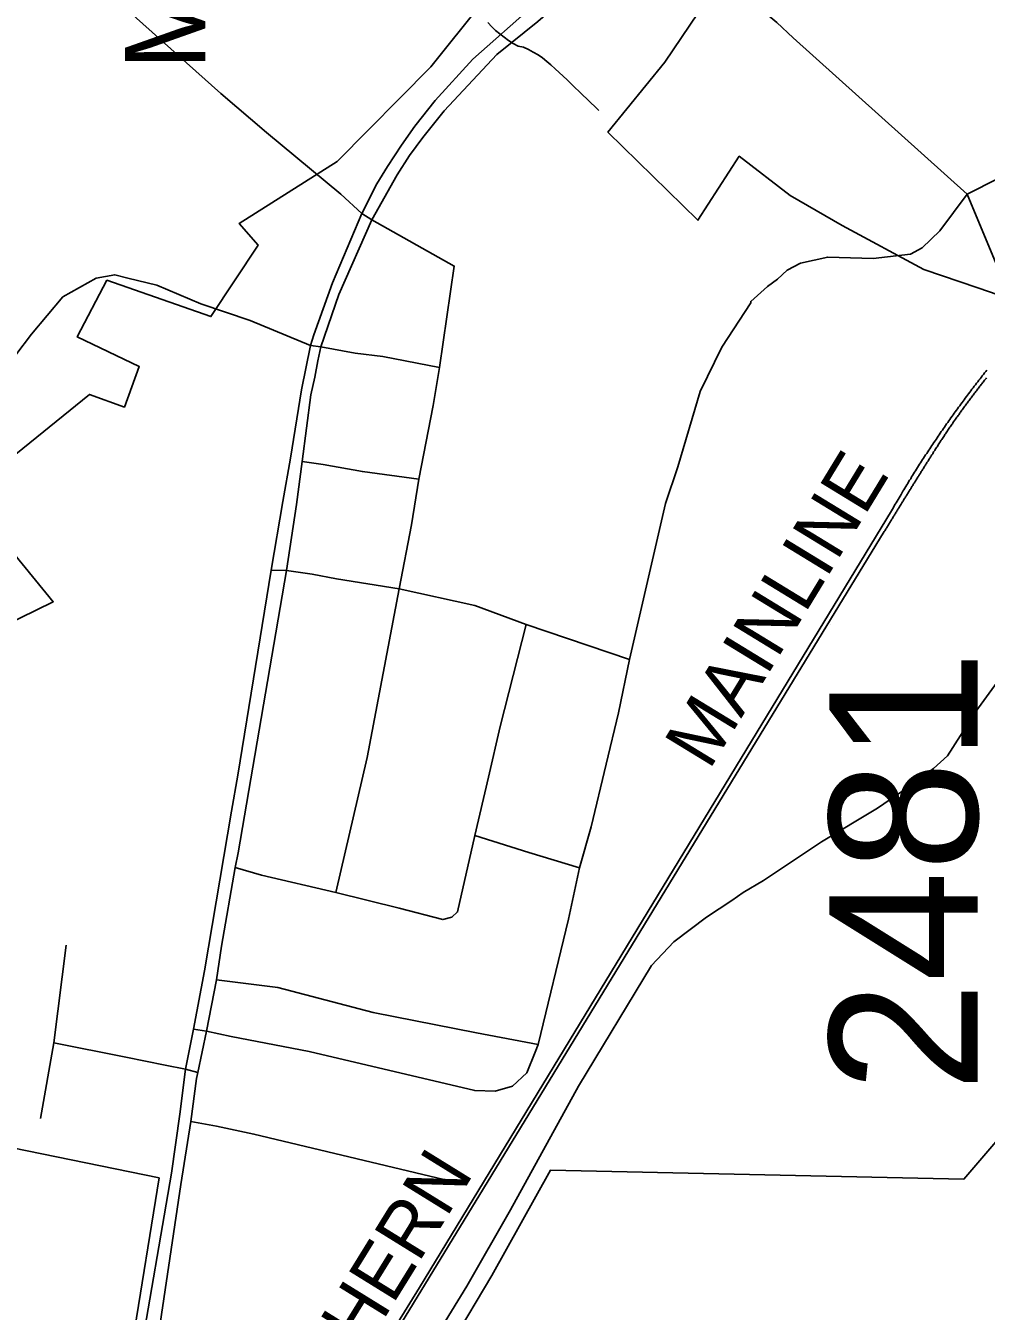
# Model space of a CAD drawing. Extents: x 1373043 to 1375788, y 550128 to 553055.
# Drawn here: x 1373223.9 to 1373314.3, y 550684.8 to 550805.7 of the extents above; entities that cross this region are included whole.
import ezdxf

# ---------------------------------------------------------------- set-up
doc = ezdxf.new("R2010")
doc.units = 0
for name, color, linetype in [('Old_Level_12', 7, 'Continuous'), ('Old_Level_14', 7, 'Continuous'), ('Old_Level_28', 7, 'Continuous'), ('Old_Level_32', 7, 'Continuous'), ('Old_Level_44', 7, 'Continuous'), ('Old_Level_48', 7, 'Continuous'), ('Old_Level_62', 7, 'Continuous'), ('Old_Level_9', 7, 'Continuous')]:
    doc.layers.add(name, color=color, linetype=linetype)

msp = doc.modelspace()

# ---------------------------------------------------------------- linework, layer by layer
at = {"layer": 'Old_Level_14'}
msp.add_line((1373299.6, 550749.45), (1373299.6, 550749.45), dxfattribs=at)
at = {"layer": 'Old_Level_28'}
for p, q in [((1373240.92, 550711.19), (1373241.85, 550716.02)), ((1373239.69, 550711.36), (1373238.96, 550707.59)), ((1373240.1, 550707.28), (1373240.92, 550711.19))]:
    msp.add_line(p, q, dxfattribs=at)
for points in [[(1373282.11, 550816.63), (1373278.35, 550813.16), (1373274.52, 550810.14), (1373271.67, 550807.62), (1373265.99, 550802.6), (1373262.43, 550798.7), (1373260.52, 550796.28), (1373259.28, 550794.52), (1373257.94, 550792.49), (1373256.94, 550790.87), (1373255.53, 550788.08)], [(1373256.48, 550787.5), (1373258.86, 550791.72), (1373260.04, 550793.52), (1373261.29, 550795.23), (1373263.28, 550797.75), (1373268.23, 550803.03), (1373272.1, 550806.14), (1373280.61, 550813.51), (1373280.75, 550813.7), (1373282.89, 550815.73)], [(1373255.53, 550788.08), (1373252.77, 550781.56), (1373251.01, 550776.67), (1373250.72, 550775.67)], [(1373251.69, 550775.53), (1373253.39, 550780.47), (1373256.48, 550787.5)], [(1373250.72, 550775.67), (1373249.86, 550771.49), (1373248.82, 550765.07), (1373248.1, 550761), (1373247, 550754.53)], [(1373249.94, 550764.76), (1373250.74, 550771.04), (1373251.12, 550772.7), (1373251.4, 550774.21), (1373251.69, 550775.53)], [(1373248.45, 550754.5), (1373249.39, 550760.72), (1373249.94, 550764.76)], [(1373247, 550754.53), (1373243.87, 550735.27), (1373243.28, 550731.88), (1373240.72, 550716.86), (1373239.69, 550711.36)], [(1373243.62, 550726.56), (1373243.89, 550727.94), (1373248.45, 550754.5)], [(1373241.85, 550716.02), (1373242.32, 550719.17), (1373243.62, 550726.56)], [(1373238.96, 550707.59), (1373238.42, 550703.37), (1373237.62, 550697.82), (1373234.6, 550680.13), (1373231.07, 550660.01)], [(1373239.46, 550702.69), (1373239.99, 550706.74), (1373240.1, 550707.28)], [(1373232.57, 550660.38), (1373236, 550679.89), (1373238.52, 550696.76), (1373239.46, 550702.69)]]:
    msp.add_lwpolyline(points, dxfattribs=at)
at = {"layer": 'Old_Level_32'}
for p, q in [((1373256.48, 550787.5), (1373255.53, 550788.08)), ((1373250.72, 550775.67), (1373251.69, 550775.53)), ((1373247, 550754.53), (1373248.45, 550754.5)), ((1373271, 550749.44), (1373280.74, 550746.13)), ((1373226.54, 550710.09), (1373227.71, 550719.27)), ((1373239.69, 550711.36), (1373240.92, 550711.19)), ((1373225.3, 550702.96), (1373226.54, 550710.09)), ((1373240.1, 550707.28), (1373238.96, 550707.59))]:
    msp.add_line(p, q, dxfattribs=at)
for points in [[(1373312.5, 550789.89), (1373315.41, 550791.38), (1373319.75, 550792.77), (1373327.67, 550794.97), (1373334.41, 550797.08), (1373339.3, 550798.67), (1373343.71, 550800.13), (1373350.28, 550802.37), (1373366.35, 550807.53), (1373371.49, 550809.06), (1373378.05, 550811.22), (1373381.15, 550812.18), (1373385.12, 550814.73), (1373386.58, 550815.99), (1373388.24, 550817.28), (1373391.43, 550821.07), (1373396.24, 550827.01), (1373405.03, 550836.86), (1373410.47, 550842.94), (1373418.29, 550852.16), (1373421.65, 550856)], [(1373255.53, 550788.08), (1373253.55, 550789.89), (1373246.56, 550795.7), (1373242.26, 550799.38), (1373233.47, 550807.25), (1373230.45, 550809.43), (1373229.43, 550810.16), (1373227.3, 550811.63), (1373226.31, 550812.39), (1373225.78, 550813.39), (1373226.26, 550815.62), (1373227.28, 550817.94)], [(1373282.89, 550815.73), (1373285.18, 550813.78), (1373288.65, 550811.17), (1373290.47, 550809.48), (1373292.26, 550807.99), (1373292.92, 550807.43), (1373294.58, 550806.04), (1373296.13, 550804.59), (1373312.5, 550789.89)], [(1373280.74, 550746.13), (1373284.13, 550760.81), (1373285.27, 550764.26), (1373287.37, 550771.33), (1373289.42, 550775.51), (1373292.15, 550779.68), (1373292.14, 550779.81), (1373293.7, 550781.22), (1373294.66, 550781.9), (1373295.58, 550782.74), (1373296.82, 550783.4), (1373299.38, 550783.98), (1373303.67, 550783.84), (1373307.18, 550784.24), (1373308.26, 550784.84), (1373309.92, 550786.46), (1373312.5, 550789.89)], [(1373312.5, 550789.89), (1373316.32, 550780.71), (1373317.99, 550777.43)], [(1373256.48, 550787.5), (1373264.23, 550783.14), (1373262.84, 550773.61)], [(1373221.47, 550772.83), (1373224.46, 550776.74), (1373227.4, 550780.24), (1373230.55, 550781.99), (1373232.29, 550782.32), (1373233.53, 550781.99), (1373236.26, 550781.33), (1373240.39, 550779.6), (1373245.02, 550778.03), (1373250.72, 550775.67)], [(1373251.69, 550775.53), (1373254.9, 550774.96), (1373257.52, 550774.63), (1373262.84, 550773.61)], [(1373262.84, 550773.61), (1373262.26, 550770.03), (1373260.91, 550763.08)], [(1373249.94, 550764.76), (1373251.9, 550764.48), (1373255.59, 550763.81), (1373260.91, 550763.08)], [(1373260.91, 550763.08), (1373260.2, 550758.79), (1373259.06, 550752.78)], [(1373248.45, 550754.5), (1373250.88, 550754.15), (1373253.17, 550753.71), (1373259.06, 550752.78)], [(1373259.06, 550752.78), (1373256.03, 550736.93), (1373253.1, 550724.23)], [(1373259.06, 550752.78), (1373266.16, 550751.22), (1373271, 550749.44)], [(1373266.17, 550729.59), (1373267.46, 550735.06), (1373268.56, 550739.83), (1373271, 550749.44)], [(1373276.01, 550726.54), (1373277.13, 550730.41), (1373278.52, 550736.28), (1373279.68, 550741.11), (1373280.74, 550746.13)], [(1373252.09, 550665.48), (1373265.43, 550687.21), (1373269.52, 550694.37), (1373275.93, 550706), (1373282.79, 550717.35), (1373284.9, 550719.58), (1373287.96, 550721.89), (1373290.35, 550723.46), (1373291.43, 550724.21), (1373293.33, 550725.36), (1373296.72, 550727.59), (1373298.79, 550729), (1373304.08, 550732.16), (1373307.13, 550734.24), (1373309.33, 550735.87), (1373310.67, 550737.07), (1373313.31, 550741.23), (1373315.32, 550743.99)], [(1373253.1, 550724.23), (1373259.04, 550722.76), (1373263.17, 550721.68), (1373264.02, 550721.91), (1373264.55, 550722.39), (1373266.17, 550729.59)], [(1373266.17, 550729.59), (1373271.24, 550727.98), (1373276.01, 550726.54)], [(1373243.62, 550726.56), (1373246.1, 550725.85), (1373253.1, 550724.23)], [(1373272.13, 550709.93), (1373274.99, 550721.71), (1373276.01, 550726.54)], [(1373241.85, 550716.02), (1373247.65, 550715.27), (1373256.61, 550712.92), (1373266.34, 550711.01), (1373272.13, 550709.93)], [(1373240.92, 550711.19), (1373243.23, 550710.69), (1373250.58, 550709.25), (1373266.16, 550705.59), (1373268.09, 550705.53), (1373269.71, 550706), (1373271.07, 550707.25), (1373271.84, 550709.19), (1373272.13, 550709.93)], [(1373238.96, 550707.59), (1373237.04, 550707.97), (1373233.32, 550708.73), (1373226.54, 550710.09)], [(1373239.46, 550702.69), (1373241.87, 550702.24), (1373245.39, 550701.5), (1373264.7, 550696.87)]]:
    msp.add_lwpolyline(points, dxfattribs=at)
at = {"layer": 'Old_Level_44'}
for points in [[(1373305.39, 550760.12), (1373305.48, 550760.28), (1373305.57, 550760.42), (1373305.65, 550760.58), (1373305.74, 550760.73), (1373305.83, 550760.88), (1373305.92, 550761.03), (1373306.01, 550761.19), (1373306.1, 550761.34), (1373306.19, 550761.49), (1373306.28, 550761.64), (1373306.37, 550761.79), (1373306.46, 550761.95), (1373306.55, 550762.09), (1373306.64, 550762.24), (1373306.73, 550762.4), (1373306.82, 550762.55), (1373306.91, 550762.69), (1373307, 550762.85), (1373307.09, 550763), (1373307.19, 550763.14), (1373307.28, 550763.3), (1373307.37, 550763.44), (1373307.46, 550763.59), (1373307.56, 550763.74), (1373307.65, 550763.89), (1373307.75, 550764.04), (1373307.84, 550764.19), (1373307.93, 550764.34), (1373308.03, 550764.49), (1373308.12, 550764.64), (1373308.22, 550764.78), (1373308.31, 550764.93), (1373308.41, 550765.08), (1373308.5, 550765.23), (1373308.6, 550765.37), (1373308.7, 550765.52), (1373308.79, 550765.67), (1373308.89, 550765.81), (1373308.99, 550765.96), (1373309.09, 550766.11), (1373309.18, 550766.26), (1373309.28, 550766.4), (1373309.38, 550766.55), (1373309.48, 550766.69), (1373309.58, 550766.84), (1373309.67, 550766.98), (1373309.78, 550767.13), (1373309.87, 550767.27), (1373309.97, 550767.42), (1373310.07, 550767.57), (1373310.17, 550767.71), (1373310.27, 550767.86), (1373310.37, 550768), (1373310.47, 550768.15), (1373310.57, 550768.29), (1373310.68, 550768.43), (1373310.78, 550768.58), (1373310.88, 550768.72), (1373310.98, 550768.86), (1373311.08, 550769.01), (1373311.19, 550769.15), (1373311.29, 550769.29), (1373311.39, 550769.44), (1373311.5, 550769.58), (1373311.6, 550769.72), (1373311.7, 550769.86), (1373311.81, 550770), (1373311.91, 550770.15), (1373312.02, 550770.29), (1373312.12, 550770.43), (1373312.22, 550770.57), (1373312.33, 550770.71), (1373312.43, 550770.86), (1373312.54, 550770.99), (1373312.64, 550771.13), (1373312.75, 550771.28), (1373312.86, 550771.41), (1373312.96, 550771.56), (1373313.07, 550771.69), (1373313.18, 550771.83), (1373313.28, 550771.97), (1373313.39, 550772.12), (1373313.5, 550772.25), (1373313.61, 550772.39), (1373313.72, 550772.53), (1373313.83, 550772.67), (1373313.93, 550772.81), (1373314.04, 550772.95), (1373314.15, 550773.08), (1373314.26, 550773.22), (1373314.37, 550773.36)], [(1373314.34, 550772.64), (1373314.28, 550772.56), (1373314.21, 550772.48), (1373314.14, 550772.4), (1373314.08, 550772.32), (1373314.02, 550772.23), (1373313.95, 550772.15), (1373313.89, 550772.07), (1373313.82, 550771.99), (1373313.76, 550771.91), (1373313.7, 550771.83), (1373313.63, 550771.74), (1373313.57, 550771.66), (1373313.51, 550771.58), (1373313.44, 550771.5), (1373313.38, 550771.41), (1373313.31, 550771.33), (1373313.25, 550771.25), (1373313.19, 550771.17), (1373313.13, 550771.08), (1373313.06, 550771), (1373313, 550770.92), (1373312.94, 550770.84), (1373312.88, 550770.75), (1373312.81, 550770.67), (1373312.75, 550770.59), (1373312.69, 550770.5), (1373312.63, 550770.42), (1373312.57, 550770.34), (1373312.5, 550770.25), (1373312.44, 550770.17), (1373312.38, 550770.09), (1373312.32, 550770), (1373312.26, 550769.92), (1373312.2, 550769.84), (1373312.13, 550769.75), (1373312.07, 550769.66), (1373312.01, 550769.58), (1373311.95, 550769.5), (1373311.89, 550769.41), (1373311.83, 550769.33), (1373311.77, 550769.24), (1373311.71, 550769.16), (1373311.65, 550769.08), (1373311.59, 550768.99), (1373311.53, 550768.91), (1373311.47, 550768.82), (1373311.41, 550768.74), (1373311.35, 550768.65), (1373311.29, 550768.57), (1373311.23, 550768.48), (1373311.17, 550768.39), (1373311.12, 550768.31), (1373311.06, 550768.22), (1373311, 550768.14), (1373310.94, 550768.06), (1373310.88, 550767.97), (1373310.82, 550767.88), (1373310.76, 550767.79), (1373310.7, 550767.71), (1373310.65, 550767.63), (1373310.59, 550767.54), (1373310.53, 550767.45), (1373310.47, 550767.36), (1373310.41, 550767.28), (1373310.36, 550767.19), (1373310.3, 550767.11), (1373310.24, 550767.02), (1373310.18, 550766.93), (1373310.13, 550766.84), (1373310.07, 550766.76), (1373310.01, 550766.67), (1373309.96, 550766.59), (1373309.9, 550766.5), (1373309.84, 550766.41), (1373309.79, 550766.33), (1373309.73, 550766.23), (1373309.67, 550766.15), (1373309.62, 550766.06), (1373309.56, 550765.98), (1373309.5, 550765.89), (1373309.45, 550765.8)], [(1373309.45, 550765.8), (1373309.4, 550765.72), (1373309.35, 550765.65), (1373309.3, 550765.57), (1373309.26, 550765.49), (1373309.21, 550765.42), (1373309.16, 550765.34), (1373309.11, 550765.26), (1373309.06, 550765.19), (1373309.01, 550765.11), (1373308.96, 550765.04), (1373308.92, 550764.96), (1373308.87, 550764.88), (1373308.82, 550764.8), (1373308.77, 550764.73), (1373308.72, 550764.65), (1373308.68, 550764.57), (1373308.63, 550764.5), (1373308.58, 550764.42), (1373308.53, 550764.34), (1373308.48, 550764.27), (1373308.43, 550764.19), (1373308.39, 550764.11), (1373308.34, 550764.04), (1373308.29, 550763.96), (1373308.24, 550763.88), (1373308.19, 550763.81), (1373308.14, 550763.73), (1373308.1, 550763.65), (1373308.05, 550763.57), (1373308, 550763.5), (1373307.95, 550763.42), (1373307.9, 550763.35), (1373307.86, 550763.27), (1373307.81, 550763.19), (1373307.76, 550763.11), (1373307.71, 550763.04), (1373307.66, 550762.96), (1373307.62, 550762.89), (1373307.57, 550762.81), (1373307.52, 550762.73), (1373307.47, 550762.65), (1373307.42, 550762.58), (1373307.38, 550762.5), (1373307.33, 550762.42), (1373307.28, 550762.35), (1373307.23, 550762.27), (1373307.19, 550762.19), (1373307.14, 550762.11), (1373307.09, 550762.04), (1373307.04, 550761.96), (1373306.99, 550761.88), (1373306.95, 550761.81), (1373306.9, 550761.73), (1373306.85, 550761.65), (1373306.8, 550761.57), (1373306.75, 550761.5), (1373306.71, 550761.42), (1373306.66, 550761.34), (1373306.61, 550761.27), (1373306.56, 550761.19), (1373306.52, 550761.11), (1373306.47, 550761.03), (1373306.42, 550760.96), (1373306.37, 550760.88), (1373306.32, 550760.8), (1373306.28, 550760.73), (1373306.23, 550760.65), (1373306.18, 550760.57), (1373306.13, 550760.5), (1373306.09, 550760.41), (1373306.04, 550760.34), (1373305.99, 550760.26), (1373305.95, 550760.19), (1373305.9, 550760.11), (1373305.85, 550760.03), (1373305.8, 550759.96), (1373305.75, 550759.88), (1373305.71, 550759.8), (1373305.66, 550759.72), (1373305.61, 550759.65), (1373305.57, 550759.57), (1373305.52, 550759.49), (1373305.47, 550759.41), (1373305.42, 550759.34), (1373305.38, 550759.26), (1373305.33, 550759.18), (1373305.28, 550759.1), (1373305.23, 550759.03), (1373305.19, 550758.95), (1373305.14, 550758.87), (1373305.09, 550758.79), (1373305.04, 550758.72), (1373305, 550758.64), (1373304.95, 550758.56), (1373304.9, 550758.49), (1373304.86, 550758.41), (1373304.81, 550758.33), (1373304.76, 550758.25), (1373304.71, 550758.18)], [(1373249.69, 550668.83), (1373260.97, 550687.07), (1373275.57, 550711.1), (1373305.39, 550760.12)], [(1373304.71, 550758.18), (1373266.98, 550696.37), (1373250.18, 550668.85)]]:
    msp.add_lwpolyline(points, dxfattribs=at)
at = {"layer": 'Old_Level_48'}
msp.add_line((1373229.83, 550656.55), (1373236.46, 550697.37), dxfattribs=at)
for points in [[(1373288.18, 550825.73), (1373285.86, 550822.58), (1373283.33, 550819.76), (1373279.11, 550815.95), (1373271.35, 550809.89), (1373273.73, 550815.44), (1373271.91, 550816.03), (1373270.15, 550813.04), (1373266.83, 550807.87), (1373262.04, 550801.86), (1373253.22, 550792.97)], [(1373336.32, 550729.83), (1373332.49, 550735.39), (1373330.4, 550744.08), (1373327.27, 550757.3), (1373324.14, 550766.34), (1373322.57, 550770.17), (1373320.48, 550774.86), (1373316.48, 550779.21), (1373315.43, 550780.42), (1373313.52, 550781.09), (1373308.44, 550782.81), (1373300.74, 550786.95), (1373295.84, 550789.77), (1373291.06, 550793.47), (1373287.17, 550787.45), (1373278.7, 550795.73), (1373284.06, 550802.32), (1373290.26, 550811.52)], [(1373253.22, 550792.97), (1373244, 550787.14), (1373245.78, 550785.1), (1373241.33, 550778.38), (1373231.55, 550781.8), (1373228.76, 550776.47), (1373234.6, 550773.68), (1373233.19, 550769.87), (1373229.92, 550771.07), (1373207.41, 550752.87), (1373207.43, 550751.22)], [(1373236.46, 550697.37), (1373183.99, 550708.12), (1373180.72, 550702.36), (1373165.88, 550718.26), (1373151.49, 550732.55), (1373139.62, 550743.77), (1373124.05, 550758.84), (1373109.22, 550773.14), (1373099.99, 550781.27), (1373088.48, 550768.94)], [(1373207.43, 550751.22), (1373222.9, 550755.97), (1373226.5, 550751.57), (1373207.88, 550742.46), (1373210.63, 550737.6), (1373198.07, 550740.79), (1373199.29, 550746.7)], [(1373372.48, 550663.67), (1373351.49, 550665.74), (1373346.79, 550669.73), (1373338.39, 550679.6), (1373329.66, 550687.56), (1373321.26, 550696.22), (1373317.07, 550702.97), (1373312.2, 550697.26), (1373273.31, 550698.11), (1373267.78, 550688.19), (1373260.32, 550675.67), (1373262.97, 550674.06), (1373265.75, 550669.81)]]:
    msp.add_lwpolyline(points, dxfattribs=at)
at = {"layer": 'Old_Level_62'}
msp.add_lwpolyline([(1373277.84, 550797.78), (1373277.47, 550798.14), (1373277.1, 550798.49), (1373276.72, 550798.85), (1373276.35, 550799.21), (1373275.98, 550799.57), (1373275.6, 550799.93), (1373275.23, 550800.29), (1373274.86, 550800.64), (1373274.48, 550801), (1373274.1, 550801.35), (1373273.72, 550801.7), (1373273.34, 550802.05), (1373272.95, 550802.39), (1373272.55, 550802.71), (1373272.12, 550803), (1373271.67, 550803.26), (1373271.23, 550803.52), (1373270.75, 550803.72), (1373270.25, 550803.83), (1373269.79, 550804.06), (1373269.35, 550804.34), (1373268.94, 550804.65), (1373268.53, 550804.97), (1373268.13, 550805.3), (1373267.76, 550805.65), (1373267.41, 550806.04)], dxfattribs=at)

# ---------------------------------------------------------------- texts
at = {"layer": 'Old_Level_12'}
msp.add_text('2481', height=13.952, rotation=90, dxfattribs=at).set_placement((1373313.48, 550705.46))
at = {"layer": 'Old_Level_14'}
for s, rotation, p in [('MAINLINE', 58.5976, (1373288.23, 550735.64)), ('SOUTHERN', 58.2755, (1373245.73, 550664.82))]:
    msp.add_text(s, height=5.167, rotation=rotation, dxfattribs=at).set_placement(p)
at = {"layer": 'Old_Level_9'}
msp.add_text('McADENVILLE', height=7.56, rotation=90, dxfattribs=at).set_placement((1373240.82, 550801.6))

doc.saveas('drawing.dxf')
